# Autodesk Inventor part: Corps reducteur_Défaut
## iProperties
Shininess: 64.0
Length Units: 11269
Angle Units: 11279
Time Units: 11290
Mass Units: 11283
Length Display Precision: 3
Angle Display Precision: 2
Compacted: True
Part Number: Corps reducteur_Défaut
Document SubType Name: Modeling
Created: 2006-01
Material: Par défaut
Designer: Fricot
Density: 0.0
Volumn: 0.0
Area: 0.0
PropertySet Name: Model Information
Control State: 0
Master: False
Checked Out: False
Author: Fricot
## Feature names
1. Base1
